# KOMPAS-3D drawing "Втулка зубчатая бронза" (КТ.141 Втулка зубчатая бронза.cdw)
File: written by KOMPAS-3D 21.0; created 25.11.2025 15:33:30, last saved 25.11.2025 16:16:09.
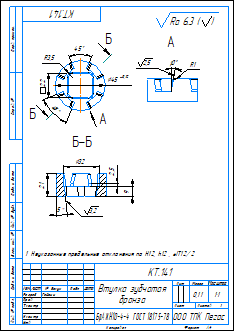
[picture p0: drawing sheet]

Sheet 1: A4, portrait

Document properties: Автор: User; Полное имя файла: C:\Users\User\Desktop\Pelorus PRO доработки\ЗАФИКСИРОВАЛИ\Втулка зубчатая бронза\КТ.141 Втулка зубчатая бронза.cdw; Знак неуказанной шероховатости: 4; Параметр неуказанной шероховатости: Ra 6.3; Масса: 0.10931

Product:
- Part/product: Втулка зубчатая бронза
    Материал: БрАЖ9-4  ГОСТ 18175-78 (density 7500 kg/m3)
    Масса: 0.10931

Title block, sheet 1: Наименование: Втулка зубчатая / бронза; designation: КТ.141; Материал: БрАЖН10-4-4  ГОСТ 18175-78; Масса: 0,11; Количество листов документа: 1; organisation: ООО ТПК Пегас; Форматы листов документа: A4; Разработал: Гайсин

Views: Вид 1, Сверху, Разрез 3, Вид по стрелке 4, Разрез Б-Б, Вид по стрелке А
Referenced files in C:\Users\User\Desktop\Pelorus PRO доработки\ЗАФИКСИРОВАЛИ\Втулка зубчатая бронза\: КТ.141 Втулка зубчатая бронза.m3d
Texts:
  Ra 6.3
  Ra 6.3 ( )
Dimensions and other numbers on the sheet: 22; 3,5; 45; 9; 2,5; 21; 32; 1; 1:1; 0,11

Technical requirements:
  Неуказанные предельные отклонения по H12, h12 ,  IT12/2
